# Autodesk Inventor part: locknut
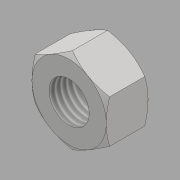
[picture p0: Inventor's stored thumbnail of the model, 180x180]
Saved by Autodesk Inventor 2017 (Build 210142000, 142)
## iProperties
Created: 2016-05
Part Number: locknut
Material: Generic
Document SubType Name: Modeling
Designer: CADCIM
Density: 1 g/cm^3
Appearance: Default
Author: CADCIM
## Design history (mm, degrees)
sketch "Sketch1"
  geometry: L1 (9.6, -5.543)-(0, -11.085); L2 (0, -11.085)-(-9.6, -5.543); L3 (-9.6, -5.543)-(-9.6, 5.543); L4 (-9.6, 5.543)-(0, 11.085); L5 (0, 11.085)-(9.6, 5.543); L6 (9.6, 5.543)-(9.6, -5.543); 2 further points
  constraints: 12 end point, 1 coincident, 1 vertical alignment, 13 other
  dimensions: "d0" = 19.2 distance between parallel lines of L3 L6
extrude "Extrusion1" new body sketch "Sketch1" distance "d1" = 10.8; taper "d2" = 0 deg
sketch "Sketch2"
  geometry: L1 (0, 11.085)-(-9.6, 5.543) reference; C1 r 9.6 at (0, 0); 1 further point
  constraints: 1 centre point, 1 coincident, 1 tangent
extrude "Extrusion2" sketch "Sketch2" distance "d3" = 10.8; taper "d4" = 60 deg
workplane "Work Plane1"
sketch "Sketch3"
  geometry: L1 (0, -11.085)-(9.6, -5.543) reference; C1 r 9.6 at (0, 0); 1 further point
  constraints: 1 centre point, 1 coincident, 1 tangent
extrude "Extrusion3" sketch "Sketch3" distance "d5" = 10.8; taper "d6" = 60 deg
sketch "Sketch4"
  geometry: 1 further point
hole "Hole1" diameter "d9" = 10.376; stored, may be unused: countersink angle "d13" = 90 deg, drill point angle "d15" = 118 deg; dims "d7" = 10, "d8" = 10, "d10" = 24, "d11" = 4, "d12" = 2, "d14" = 31.3
body "Solid1"
